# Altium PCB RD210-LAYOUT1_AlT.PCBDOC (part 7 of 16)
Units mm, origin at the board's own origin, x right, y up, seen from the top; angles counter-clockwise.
Board outline 330 x 300 mm, 6 copper layers (TOP, Mid-Layer 1, Mid-Layer 2, Mid-Layer 3, Mid-Layer 4, BOTTOM), stack 1.422 mm thick; 981 components, 463 nets, 2326 pads, 12534 vias.
Unrouted connection lines stored in the file: 6.
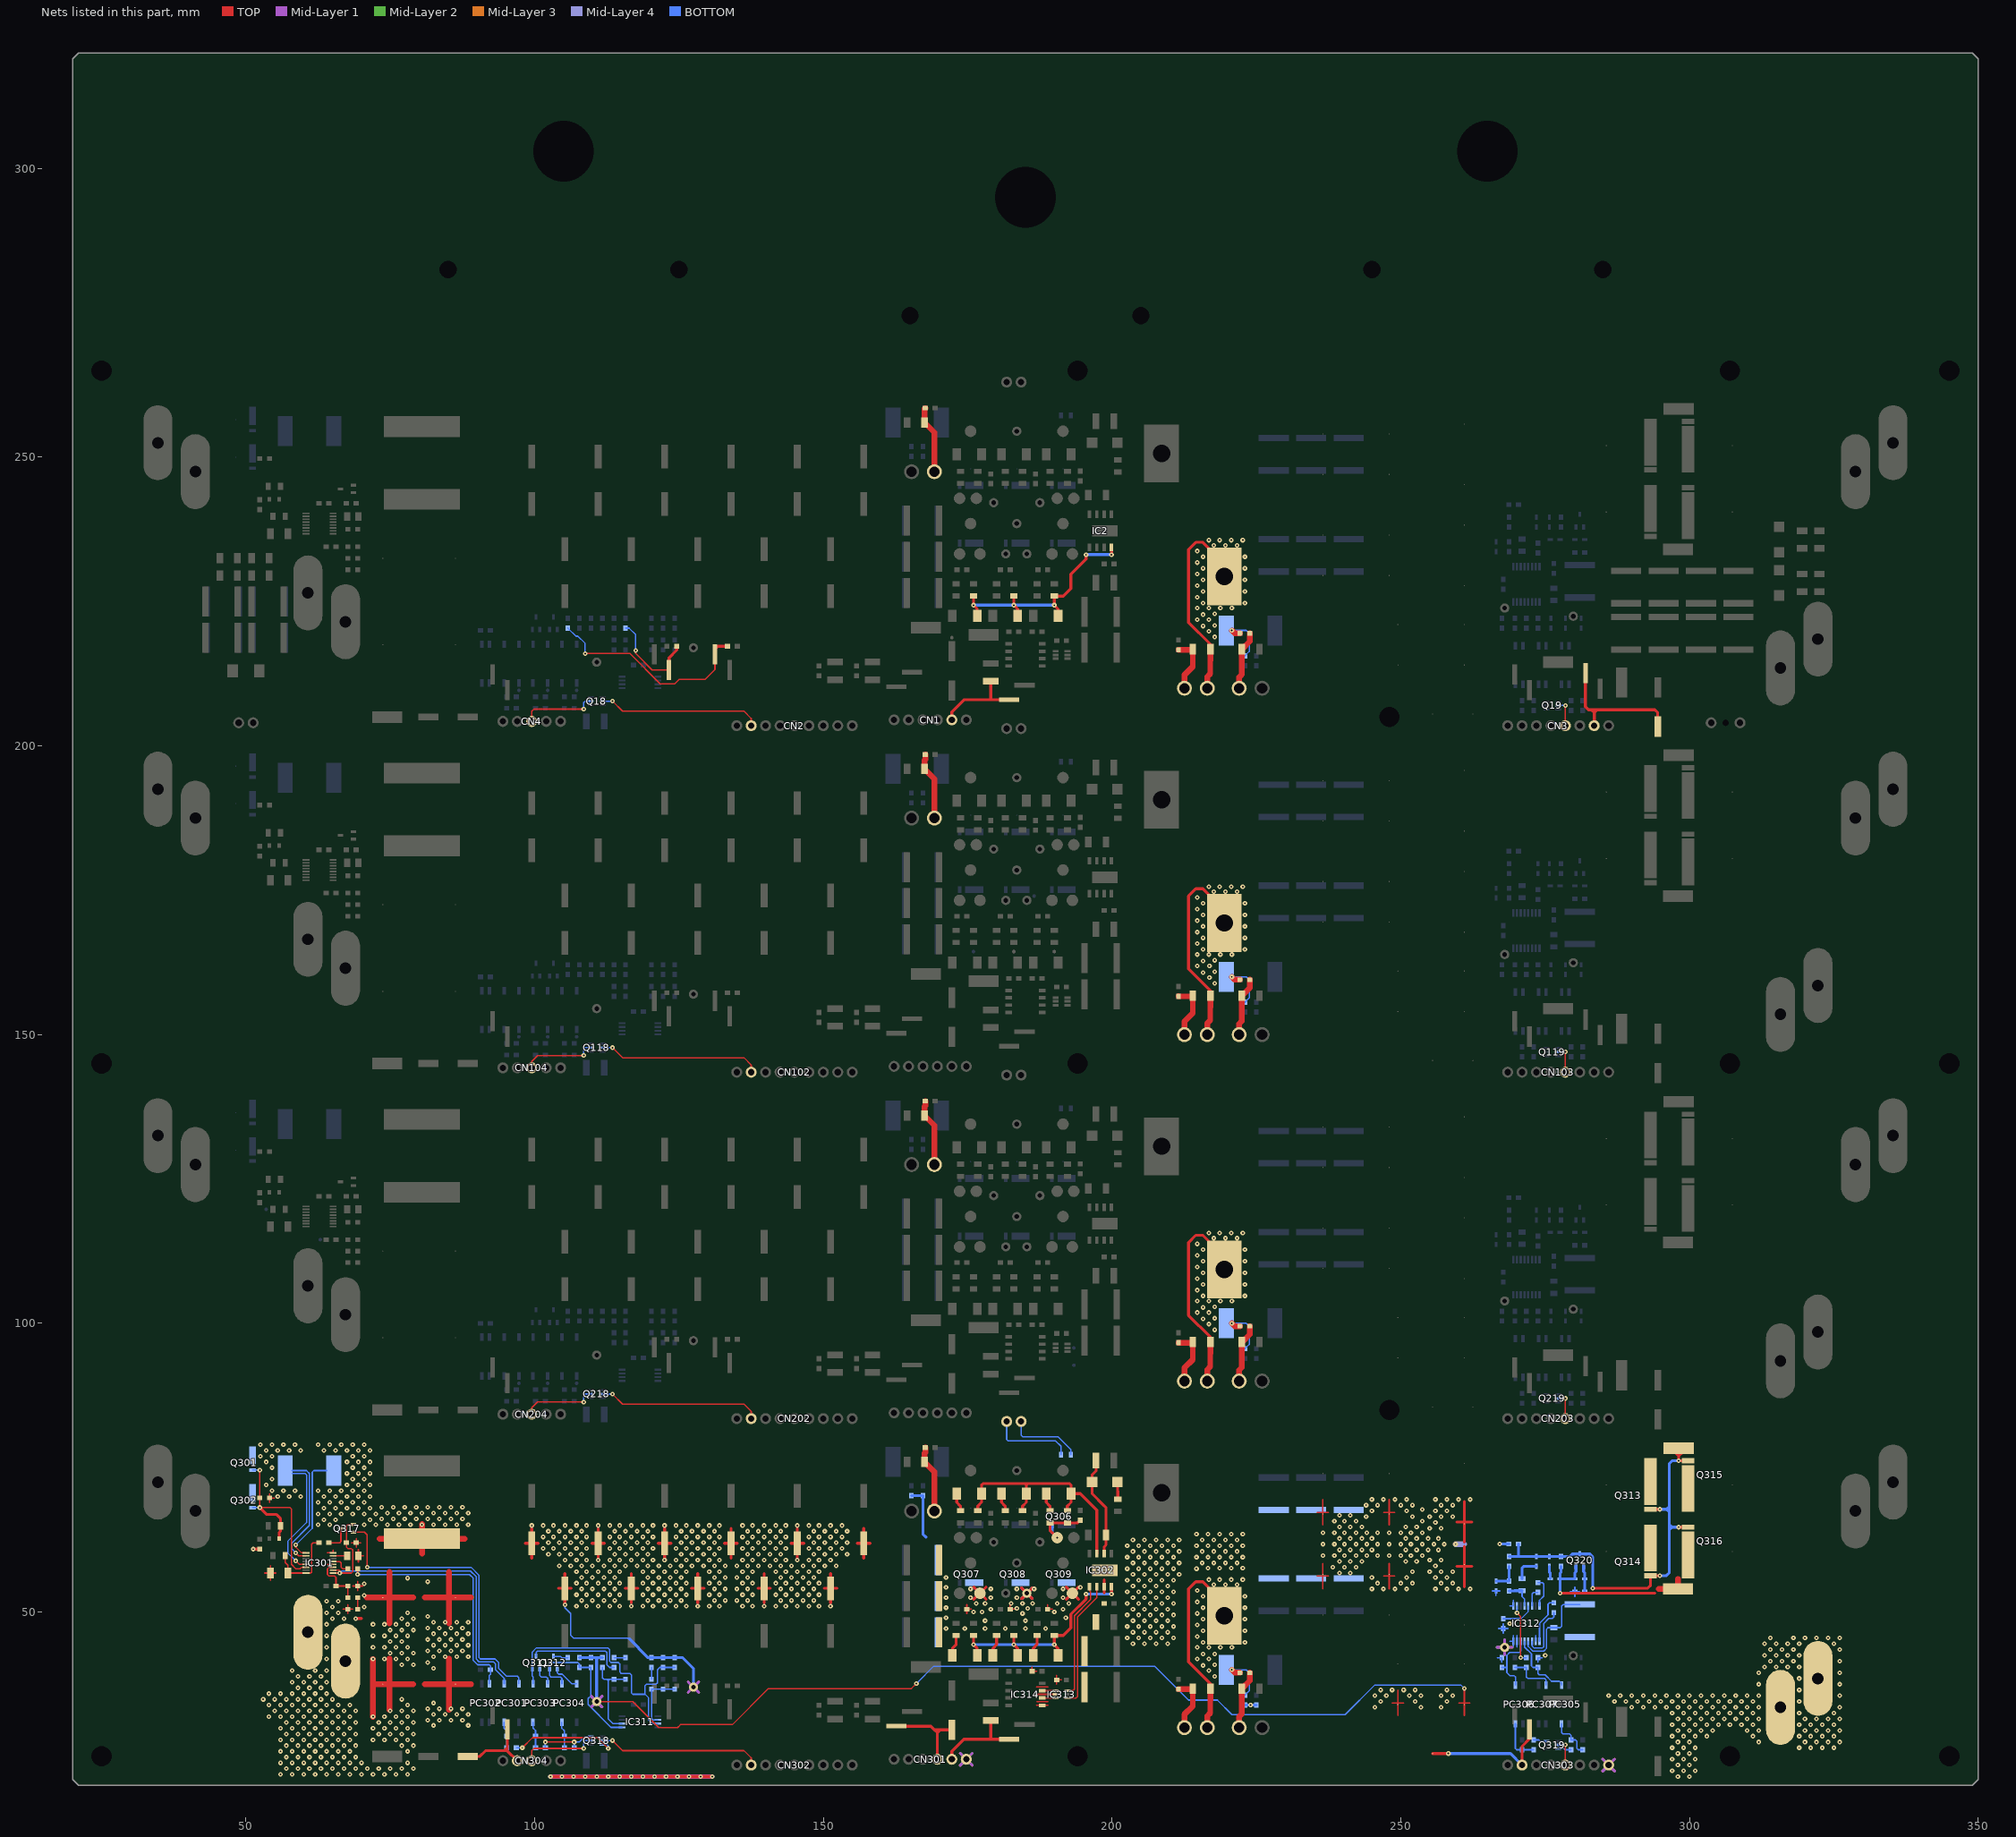
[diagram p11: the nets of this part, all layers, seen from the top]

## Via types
v1: diameter 0.8, hole 0.3, TOP to BOTTOM, 12534 vias

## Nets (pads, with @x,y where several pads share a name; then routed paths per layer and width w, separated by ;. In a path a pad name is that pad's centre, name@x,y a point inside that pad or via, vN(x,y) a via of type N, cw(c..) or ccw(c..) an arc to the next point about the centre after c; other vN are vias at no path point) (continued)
GND_P-4: C311.1 C313.1 C314.2 C315.1 C316.2 C317.2 C318.2 C319.2 C320.2 C321.2 C322.2 C323.2 C324.2 C325.2 C326.2 C327.2 C328.2 C329.1 C330.1 C331.1 C332.1 C333.1 C334.1 C335.1 C336.1 C337.2 C338.2 C339.1 C340.1 C342.2 C343.2 C349.2 C350.2 C351.2 C352.2 C353.2 C354.2 C355.2 C356.2 C357.2 C358.2 C359.1 C360.1 C361.1 C362.1 C363.1 C364.1 C379.1 C381.1 C383.2 C443.2 C447.2 CN301.6 CN303.1 CN316.1 CN317.1 CN320.1 CN334.1 D317.1 IC301.12 IC301.16 IC302.7 IC302.9 IC312.2 IC312.7 IC312.8 IC312.9 IC313.2 IC314.5 Q307.S Q308.S Q309.S R304.1 R322.2 R325.2 R328.2 R350.2 R351.1 R357.2 R358.1 R365.1 R388.1 R389.1 R393.1 TN42.1 TN42.2 TN44.1 TN44.2 TP317.1 TP319.1 | length 650.6
  TOP w0.25: 53.275,56.75 C313.1@54.225,56.75 ; 54.225,55.475 C313.1@54.225,56.75 ; 54.225,58.025 C313.1@54.225,56.75 ; 55.175,56.75 C313.1@54.225,56.75 ; 64.125,58.25 IC301.12@65.1,58.25 ; 64.125,60.25 IC301.16@65.1,60.25 65.1,60.76 ; 66.825,50.5 R304.1@67.65,50.5 ; 67.65,49.725 R304.1@67.65,50.5 ; 67.65,51.275 R304.1@67.65,50.5 ; 68.275,62 R365.1@69.1,62 ; 68.475,50.5 R304.1@67.65,50.5 ; 68.525,54.5 C315.1@69.35,54.5 ; 69.1,61.225 R365.1@69.1,62 ; 69.1,62.775 R365.1@69.1,62 ; 69.35,53.725 C315.1@69.35,54.5 ; 69.35,55.275 C315.1@69.35,54.5 ; 69.475,58.65 C314.2@69.475,59.75 ; 69.475,60.85 C314.2@69.475,59.75 ; 69.925,62 R365.1@69.1,62 ; 70.175,54.5 C315.1@69.35,54.5 ; 70.375,59.75 C314.2@69.475,59.75 ; CN317.1@110.75,34.5 117,34.5 121.5,30 124.75,30 125.25,30.5 134.25,30.5 140.5,36.75 165.25,36.75 v1(166.125,37.625) ; 174.85,49.725 R322.2@174.85,50.5 ; 174.85,51.275 R322.2@174.85,50.5 ; 175.675,50.5 R322.2@174.85,50.5 ; v1@182.35,51.275 R325.2@182.35,50.5 v1@183.175,50.5 ; 186.15,40.525 C340.1@186.15,39.75 186.975,39.75 ; 186.875,37.02 188.875,37.02 ; 186.925,33.845 IC314.5@187.9,33.845 188.875,33.845 ; 187,34.48 188.875,34.48 ; 187,35.75 IC313.2@190.225,35.75 190.89,35.75 191.17,35.47 ; 188.85,51.275 R328.2@188.85,50.5 189.675,50.5 ; 190.4,37.475 C339.1@190.4,38.25 ; 190.4,39.025 C339.1@190.4,38.25 ; 191.225,38.25 C339.1@190.4,38.25 ; 235.523,56.225 236.5,56.225 ; 235.523,67.275 236.5,67.275 ; 236.5,54.023 236.5,56.225 ; 236.5,58.427 C353.2@236.5,56.5 236.5,56.225 ; 236.5,65.073 C351.2@236.5,67 236.5,67.275 ; 236.5,69.477 236.5,67.275 ; 237.477,56.225 236.5,56.225 ; 237.477,67.275 236.5,67.275 ; 247.023,56.225 248,56.225 ; 247.023,67.275 248,67.275 ; 248,54.023 248,56.225 ; 248,58.427 C354.2@248,56.5 248,56.225 ; 248,65.073 C352.2@248,67 248,67.275 ; 248,69.477 248,67.275 ; 248.523,34.275 249.5,34.275 ; 248.977,56.225 248,56.225 ; 248.977,67.275 248,67.275 ; 249.5,32.073 C355.2@249.5,34 249.5,34.275 ; 249.5,36.477 249.5,34.275 ; 250.477,34.275 249.5,34.275 ; 260.023,34.275 261,34.275 ; 261,32.073 C356.2@261,34 261,34.275 ; v1(261,36.75) 261,34.275 ; 261.977,34.275 261,34.275
  TOP w0.5: v1(51.242,60.902) C447.2@52.385,60.902 ; v1(69,48.875) 70,48.875 ; 98.4,61.9 C318.2@99.5,61.9 ; 99.5,59.35 C318.2@99.5,61.9 ; 99.5,64.45 C318.2@99.5,61.9 ; 100.6,61.9 C318.2@99.5,61.9 ; 104.15,54.1 C328.2@105.25,54.1 ; v1(105.25,51.25) C328.2@105.25,54.1 ; 105.25,56.65 C328.2@105.25,54.1 ; 106.35,54.1 C328.2@105.25,54.1 ; 109.9,61.9 C319.2@111,61.9 ; v1@111,59.35 C319.2@111,61.9 ; 111,64.45 C319.2@111,61.9 ; 112.1,61.9 C319.2@111,61.9 ; 115.65,54.1 C327.2@116.75,54.1 ; 116.75,51.55 C327.2@116.75,54.1 ; 116.75,56.65 C327.2@116.75,54.1 ; 117.85,54.1 C327.2@116.75,54.1 ; 121.4,61.9 C320.2@122.5,61.9 ; v1@122.5,59.35 C320.2@122.5,61.9 ; 122.5,64.45 C320.2@122.5,61.9 ; 123.6,61.9 C320.2@122.5,61.9 ; 127.15,54.1 C326.2@128.25,54.1 ; 128.25,51.55 C326.2@128.25,54.1 ; 128.25,56.65 C326.2@128.25,54.1 ; 129.35,54.1 C326.2@128.25,54.1 ; 132.9,61.9 C321.2@134,61.9 ; 134,59.35 C321.2@134,61.9 ; 134,64.45 C321.2@134,61.9 ; 135.1,61.9 C321.2@134,61.9 ; 138.65,54.1 C325.2@139.75,54.1 ; 139.75,51.55 C325.2@139.75,54.1 ; 139.75,56.65 C325.2@139.75,54.1 ; 140.85,54.1 C325.2@139.75,54.1 ; 144.4,61.9 C322.2@145.5,61.9 ; v1@145.5,59.35 C322.2@145.5,61.9 ; 145.5,64.45 C322.2@145.5,61.9 ; 146.6,61.9 C322.2@145.5,61.9 ; 150.15,54.1 C324.2@151.25,54.1 ; 151.25,51.55 C324.2@151.25,54.1 ; 151.25,56.65 C324.2@151.25,54.1 ; 152.35,54.1 C324.2@151.25,54.1 ; 155.9,61.9 C323.2@157,61.9 ; 157,59.35 C323.2@157,61.9 ; 157,64.45 C323.2@157,61.9 ; 158.1,61.9 C323.2@157,61.9 ; 176.064,52.189 TP317.1@177.125,53.25 ; 176.064,54.311 TP317.1@177.125,53.25 ; 178.186,52.189 TP317.1@177.125,53.25 ; 178.186,54.311 TP317.1@177.125,53.25 ; 184.331,52.331 CN334.1@185.25,53.25 ; 184.331,54.169 CN334.1@185.25,53.25 ; 186.125,52.375 CN334.1@185.25,53.25 ; v1@186.169,54.169 CN334.1@185.25,53.25 ; 192.064,52.189 TP319.1@193.125,53.25 ; 192.064,54.311 TP319.1@193.125,53.25 ; 194.186,52.189 TP319.1@193.125,53.25 ; v1@194.186,54.311 TP319.1@193.125,53.25 ; 198.635,53.25 IC302.7@198.635,54.4 198.635,55.55 ; 259.696,57.9 261,57.9 ; 259.696,65.6 261,65.6 ; 261,54.396 261,57.9 ; 261,61.404 C358.2@261,58.25 261,57.9 ; 261,62.096 C357.2@261,65.25 261,65.6 ; 261,69.104 261,65.6 ; 262.304,57.9 261,57.9 ; 262.304,65.6 261,65.6
  TOP w0.6: v1(102.75,21.5) v1(104.75,21.5) v1(106.75,21.5) v1(108.75,21.5) v1(110.75,21.5) v1(112.75,21.5) v1(114.75,21.5) v1(116.75,21.5) v1(118.75,21.5) v1(120.75,21.5) v1(122.75,21.5) v1(124.75,21.5) v1(126.75,21.5) v1(128.75,21.5) v1(130.75,21.5)
  TOP w1: 70.875,52.5 C316.2@73.7,52.5 74.85,52.5 ; v1(72,31.875) 72,37.5 ; v1(72,41.875) 72,37.5 ; v1@74.85,33.043 74.85,37.5 ; 74.85,41.957 74.85,37.5 ; 74.85,48.043 74.85,52.5 ; 74.85,56.957 74.85,52.5 ; 79,37.5 74.85,37.5 ; 79,52.5 74.85,52.5 ; 72,37.5 C317.2@73.7,37.5 74.85,37.5
  Mid-Layer 1 w0.5: 109.831,33.581 CN317.1@110.75,34.5 ; 109.831,35.419 CN317.1@110.75,34.5 ; 111.669,33.581 CN317.1@110.75,34.5 ; 111.669,35.419 CN317.1@110.75,34.5 ; 126.581,36.081 CN316.1@127.5,37 ; 126.581,37.919 CN316.1@127.5,37 ; 128.419,36.081 CN316.1@127.5,37 ; 128.419,37.919 CN316.1@127.5,37 ; 173.725,23.475 CN301.6@174.75,24.5 ; 173.725,25.525 CN301.6@174.75,24.5 ; 175.775,23.475 CN301.6@174.75,24.5 ; 175.775,25.525 CN301.6@174.75,24.5 ; 184.331,52.331 CN334.1@185.25,53.25 ; 184.331,54.169 CN334.1@185.25,53.25 ; 186.169,52.331 CN334.1@185.25,53.25 ; v1@186.169,54.169 CN334.1@185.25,53.25 ; 266.7,43.875 CN320.1@268,43.875 ; 268,42.575 CN320.1@268,43.875 ; 268,45.175 CN320.1@268,43.875 ; 269.3,43.875 CN320.1@268,43.875 ; 284.975,22.475 CN303.1@286,23.5 ; 284.975,24.525 CN303.1@286,23.5 ; 287.025,22.475 CN303.1@286,23.5 ; 287.025,24.525 CN303.1@286,23.5
  Mid-Layer 1 w0.8: v1(102.75,21.5) v1(104.75,21.5) v1(106.75,21.5) v1(108.75,21.5) v1(110.75,21.5) v1(112.75,21.5) v1(114.75,21.5) v1(116.75,21.5) v1(118.75,21.5) v1(120.75,21.5) v1(122.75,21.5) v1(124.75,21.5) v1(126.75,21.5) v1(128.75,21.5) v1(130.75,21.5)
  Mid-Layer 2 w0.5: 173.725,23.475 CN301.6@174.75,24.5 ; 173.725,25.525 CN301.6@174.75,24.5 ; 175.775,23.475 CN301.6@174.75,24.5 ; 175.775,25.525 CN301.6@174.75,24.5 ; 184.331,52.331 CN334.1@185.25,53.25 ; 184.331,54.169 CN334.1@185.25,53.25 ; 186.169,52.331 CN334.1@185.25,53.25 ; v1@186.169,54.169 CN334.1@185.25,53.25 ; 266.7,43.875 CN320.1@268,43.875 ; 268,42.575 CN320.1@268,43.875 ; 268,45.175 CN320.1@268,43.875 ; 269.3,43.875 CN320.1@268,43.875 ; 284.975,22.475 CN303.1@286,23.5 ; 284.975,24.525 CN303.1@286,23.5 ; 287.025,22.475 CN303.1@286,23.5 ; 287.025,24.525 CN303.1@286,23.5
  Mid-Layer 3 w0.5: 173.725,23.475 CN301.6@174.75,24.5 ; 173.725,25.525 CN301.6@174.75,24.5 ; 175.775,23.475 CN301.6@174.75,24.5 ; 175.775,25.525 CN301.6@174.75,24.5 ; 184.331,52.331 CN334.1@185.25,53.25 ; 184.331,54.169 CN334.1@185.25,53.25 ; 186.169,52.331 CN334.1@185.25,53.25 ; v1@186.169,54.169 CN334.1@185.25,53.25 ; 266.7,43.875 CN320.1@268,43.875 ; 268,42.575 CN320.1@268,43.875 ; 268,45.175 CN320.1@268,43.875 ; 269.3,43.875 CN320.1@268,43.875 ; 284.975,22.475 CN303.1@286,23.5 ; 284.975,24.525 CN303.1@286,23.5 ; 287.025,22.475 CN303.1@286,23.5 ; 287.025,24.525 CN303.1@286,23.5
  Mid-Layer 4 w1: v1(259.5,61.75) 261,61.75
  BOTTOM w0.25: v1(105.25,51.25) 105.25,50.75 106.25,49.75 106.25,46 106.75,45.5 116.25,45.5 116.375,45.375 ; v1(166.125,37.625) 169.125,40.625 207.375,40.625 213.25,34.75 218.25,34.75 220.75,32.25 240.375,32.25 245.5,37.375 260.375,37.375 v1(261,36.75) ; 265.875,53.65 D317.1@266.5,53.65 ; 266.5,52.825 D317.1@266.5,53.65 ; 266.725,42.1 R388.1@267.5,42.1 267.5,41.275 ; 266.975,47.15 C383.2@267.75,47.15 ; 267.125,53.65 D317.1@266.5,53.65 ; 267.75,46.325 C383.2@267.75,47.15 ; 267.75,47.975 C383.2@267.75,47.15 ; 268.525,47.15 C383.2@267.75,47.15 ; 268.9,44.95 IC312.8@269.475,44.95 ; 268.9,51.05 IC312.9@269.475,51.05 269.475,52.075 ; 269.475,43.925 IC312.8@269.475,44.95 ; 269.475,45.975 IC312.8@269.475,44.95 ; 270.125,43.925 IC312.7@270.125,44.95 270.125,45.975 ; IC312.2@273.375,44.95 273.375,45.975 ; 273.75,41.275 R389.1@273.75,42.1 274.525,42.1 ; 279.325,53.5 R393.1@280.15,53.5 ; 280.15,52.725 R393.1@280.15,53.5 ; 280.15,54.275 R393.1@280.15,53.5 ; 280.975,53.5 R393.1@280.15,53.5
  BOTTOM w0.5: C379.1@107.75,42.1 R357.2@109.75,42.1 110.5,42.1 ; CN317.1@110.75,34.5 110.75,41.85 ; R358.1@111.75,42.1 111,42.1 ; 116.375,45.375 119.65,42.1 R351.1@120.25,42.1 C311.1@122.25,42.1 R350.2@124.25,42.1 125.65,42.1 127.5,40.25 CN316.1@127.5,37 ; C343.2@165.25,70.15 C342.2@167.25,70.15 167.25,63.5 167.75,63 ; 184.331,52.331 CN334.1@185.25,53.25 ; 184.331,54.169 CN334.1@185.25,53.25 ; 186.169,52.331 CN334.1@185.25,53.25 ; v1@186.169,54.169 CN334.1@185.25,53.25 ; C349.2@223,33.9 v1(224,33.9) C350.2@225,33.9 ; 266.7,43.875 CN320.1@268,43.875 268,45.175 ; v1(267.142,61.775) C443.2@268.705,61.775 ; 110.5,42.1 110.75,41.85 ; 110.5,42.1 111,42.1 ; 110.75,41.85 111,42.1
  BOTTOM w0.6: v1(102.75,21.5) v1(104.75,21.5) v1(106.75,21.5) v1(108.75,21.5) v1(110.75,21.5) v1(112.75,21.5) v1(114.75,21.5) v1(116.75,21.5) v1(118.75,21.5) v1(120.75,21.5) v1(122.75,21.5) v1(124.75,21.5) v1(126.75,21.5) v1(128.75,21.5) v1(130.75,21.5)
  other v1: 298,21.5 300,21.5 56,21.875 58,21.875 60,21.875 62,21.875 64,21.875 66,21.875 68,21.875 70,21.875 72,21.875 74,21.875 76,21.875 78,21.875 297,22.5 299,22.5 301,22.5 57,22.875 59,22.875 61,22.875 63,22.875 65,22.875 67,22.875 69,22.875 71,22.875 73,22.875 75,22.875 77,22.875 79,22.875 298,23.5 300,23.5 56,23.875 58,23.875 60,23.875 62,23.875 64,23.875 66,23.875 68,23.875 70,23.875 78,23.875 297,24.5 299,24.5 301,24.5 57,24.875 59,24.875 61,24.875 63,24.875 65,24.875 67,24.875 69,24.875 298,25.5 300,25.5 56,25.875 58,25.875 60,25.875 62,25.875 64,25.875 66,25.875 68,25.875 78,25.875 297,26.5 299,26.5 301,26.5 319,26.5 321,26.5 323,26.5 325,26.5 57,26.875 59,26.875 61,26.875 63,26.875 65,26.875 67,26.875 69,26.875 77,26.875 79,26.875 298,27.5 300,27.5 312,27.5 320,27.5 322,27.5 324,27.5 326,27.5 56,27.875 58,27.875 60,27.875 62,27.875 64,27.875 66,27.875 68,27.875 72,27.875 74,27.875 76,27.875 78,27.875 297,28.5 299,28.5 301,28.5 303,28.5 311,28.5 319,28.5 321,28.5 323,28.5 325,28.5 57,28.875 59,28.875 61,28.875 63,28.875 65,28.875 67,28.875 69,28.875 73,28.875 75,28.875 77,28.875 79,28.875 298,29.5 300,29.5 302,29.5 304,29.5 310,29.5 312,29.5 320,29.5 322,29.5 324,29.5 326,29.5 56,29.875 58,29.875 60,29.875 62,29.875 64,29.875 66,29.875 68,29.875 72,29.875 74,29.875 76,29.875 78,29.875 297,30.5 299,30.5 301,30.5 303,30.5 305,30.5 307,30.5 309,30.5 311,30.5 319,30.5 321,30.5 323,30.5 325,30.5 57,30.875 59,30.875 61,30.875 63,30.875 65,30.875 67,30.875 69,30.875 73,30.875 75,30.875 77,30.875 79,30.875 298,31.5 300,31.5 302,31.5 304,31.5 306,31.5 308,31.5 310,31.5 312,31.5 320,31.5 322,31.5 324,31.5 326,31.5 54,31.875 56,31.875 58,31.875 60,31.875 62,31.875 64,31.875 66,31.875 68,31.875 74,31.875 76,31.875 78,31.875 297,32.5 299,32.5 301,32.5 303,32.5 305,32.5 307,32.5 309,32.5 311,32.5 319,32.5 325,32.5 55,32.875 57,32.875 59,32.875 61,32.875 63,32.875 65,32.875 67,32.875 69,32.875 75,32.875 77,32.875 79,32.875 245.5,33.5 253.5,33.5 257,33.5 290,33.5 292,33.5 294,33.5 296,33.5 298,33.5 300,33.5 302,33.5 304,33.5 306,33.5 308,33.5 310,33.5 312,33.5 326,33.5 54,33.875 56,33.875 58,33.875 60,33.875 62,33.875 64,33.875 66,33.875 68,33.875 78,33.875 246.5,34.5 252.5,34.5 258,34.5 287,34.5 289,34.5 291,34.5 293,34.5 295,34.5 297,34.5 299,34.5 301,34.5 303,34.5 305,34.5 307,34.5 309,34.5 311,34.5 319,34.5 53,34.875 55,34.875 57,34.875 59,34.875 61,34.875 63,34.875 65,34.875 77,34.875 245.5,35.5 247.5,35.5 251.5,35.5 253.5,35.5 257,35.5 259,35.5 286,35.5 288,35.5 290,35.5 292,35.5 294,35.5 296,35.5 298,35.5 300,35.5 302,35.5 304,35.5 306,35.5 308,35.5 310,35.5 312,35.5 326,35.5 54,35.875 56,35.875 58,35.875 60,35.875 62,35.875 64,35.875 246.5,36.5 248.5,36.5 250.5,36.5 252.5,36.5 258,36.5 319,36.5 59,36.875 61,36.875 63,36.875 312,37.5 326,37.5 58,37.875 60,37.875 62,37.875 64,37.875 319,38.5 59,38.875 61,38.875 63,38.875 312,39.5 326,39.5 58,39.875 62,39.875 64,39.875 313,40.5 315,40.5 317,40.5 319,40.5 77,40.875 79,40.875 314,41.5 316,41.5 318,41.5 326,41.5 64,41.875 74,41.875 76,41.875 78,41.875 275,42.5 313,42.5 315,42.5 317,42.5 319,42.5 75,42.875 77,42.875 79,42.875 314,43.5 316,43.5 318,43.5 326,43.5 64,43.875 72,43.875 74,43.875 76,43.875 78,43.875 203.625,44.5 205.625,44.5 207.625,44.5 209.625,44.5 313,44.5 315,44.5 317,44.5 319,44.5 325,44.5 75,44.875 77,44.875 202.625,45.5 204.625,45.5 206.625,45.5 208.625,45.5 210.625,45.5 314,45.5 318,45.5 320,45.5 322,45.5 324,45.5 326,45.5 64,45.875 72,45.875 74,45.875 76,45.875 78,45.875 203.625,46.5 205.625,46.5 207.625,46.5 209.625,46.5 75,46.875 77,46.875 79,46.875 171.25,47.125 174.5,47.125 178,47.125 181.5,47.125 185,47.125 188.5,47.125 202.625,47.5 204.625,47.5 206.625,47.5 208.625,47.5 210.625,47.5 64,47.875 72,47.875 74,47.875 76,47.875 78,47.875 268.875,48 178,48.5 185,48.5 203.625,48.5 205.625,48.5 207.625,48.5 209.625,48.5 65,48.875 67,48.875 77,48.875 79,48.875 171.25,49 192,49 202.625,49.5 204.625,49.5 206.625,49.5 208.625,49.5 210.625,49.5 184.5,49.75 64,49.875 66,49.875 78,49.875 176,50 177.5,50 190,50 179,50.5 191.5,50.5 203.625,50.5 205.625,50.5 207.625,50.5 209.625,50.5 183.5,50.625 185.375,50.625 171.25,50.75 65,50.875 70.5,50.875 107.25,51 109,51 111,51 113,51 114.75,51 116.75,51 118.75,51 120.5,51 122.5,51 124.5,51 126.25,51 128.25,51 130.25,51 132,51 136,51 137.75,51 139.75,51 141.75,51 143.5,51 145.5,51 147.5,51 149.25,51 151.25,51 176.5,51.5 178,51.5 182.5,51.5 184.5,51.5 186.25,51.5 190.5,51.5 192.5,51.5 202.625,51.5 204.625,51.5 206.625,51.5 208.625,51.5 210.625,51.5 64,51.875 66,51.875 108.125,52 110,52 112,52 113.875,52 119.625,52 121.5,52 123.5,52 125.375,52 131.125,52 133,52 135,52 136.875,52 142.625,52 144.5,52 146.5,52 148.375,52 171.25,52.5 175.5,52.5 179,52.5 183.5,52.5 191.5,52.5 203.625,52.5 205.625,52.5 207.625,52.5 209.625,52.5 70.5,52.875 107.25,53 109,53 111,53 113,53 114.75,53 118.75,53 120.5,53 122.5,53 124.5,53 126.25,53 130.25,53 132,53 136,53 137.75,53 141.75,53 143.5,53 145.5,53 147.5,53 149.25,53 202.625,53.5 204.625,53.5 206.625,53.5 208.625,53.5 210.625,53.5 108.125,54 110,54 112,54 113.875,54 119.625,54 121.5,54 123.5,54 125.375,54 131.125,54 133,54 135,54 136.875,54 142.625,54 144.5,54 146.5,54 148.375,54 175.5,54 179,54 183.5,54 186.5,54 191.5,54 245,54 247,54 249,54 251,54 256,54 258,54 260,54 262,54 171.25,54.25 194.5,54.25 203.625,54.5 205.625,54.5 207.625,54.5 209.625,54.5 70.5,54.875 107.25,55 109,55 111,55 113,55 114.75,55 118.75,55 120.5,55 122.5,55 124.5,55 126.25,55 130.25,55 132,55 136,55 137.75,55 141.75,55 143.5,55 145.5,55 147.5,55 149.25,55 246,55 250,55 252,55 257,55 259,55 202.625,55.5 204.625,55.5 206.625,55.5 208.625,55.5 210.625,55.5 78,55.875 108.125,56 110,56 112,56 113.875,56 119.625,56 121.5,56 123.5,56 125.375,56 131.125,56 133,56 135,56 136.875,56 142.625,56 144.5,56 146.5,56 148.375,56 171.25,56 245,56 251,56 256,56 258,56 203.625,56.5 205.625,56.5 207.625,56.5 209.625,56.5 211.625,56.5 239.375,56.75 241.25,56.75 107.25,57 109,57 111,57 113,57 114.75,57 118.75,57 120.5,57 122.5,57 124.5,57 126.25,57 130.25,57 132,57 136,57 137.75,57 141.75,57 143.5,57 145.5,57 147.5,57 149.25,57 252,57 255,57 257,57 259,57 202.625,57.5 204.625,57.5 206.625,57.5 208.625,57.5 210.625,57.5 214.625,57.5 216.625,57.625 218.625,57.625 220.625,57.625 222.625,57.625 238.25,57.75 240.25,57.75 242.25,57.75 104.25,58 106.25,58 108.125,58 110,58 112,58 113.875,58 115.75,58 117.75,58 119.625,58 121.5,58 123.5,58 125.375,58 127.25,58 129.25,58 131.125,58 133,58 135,58 136.875,58 138.75,58 140.75,58 142.625,58 144.5,58 146.5,58 148.375,58 150.25,58 152.25,58 256,58 203.625,58.5 205.625,58.5 207.625,58.5 209.625,58.5 211.625,58.5 215.625,58.5 217.625,58.5 219.625,58.5 221.625,58.5 239.375,58.75 241.25,58.75 243.25,58.75 250.875,58.75 252.75,58.75 105.25,59 107.25,59 109,59 111,59 113,59 114.75,59 116.75,59 118.75,59 120.5,59 122.5,59 124.5,59 126.25,59 128.25,59 130.25,59 132,59 136,59 137.75,59 139.75,59 141.75,59 143.5,59 145.5,59 147.5,59 149.25,59 151.25,59 255,59 257,59 202.625,59.5 204.625,59.5 206.625,59.5 208.625,59.5 210.625,59.5 214.625,59.5 216.625,59.5 218.625,59.5 220.625,59.5 222.625,59.5 236.5,59.75 238.5,59.75 240.25,59.75 242.25,59.75 244.125,59.75 246,59.75 248,59.75 250,59.75 251.75,59.75 253.75,59.75 102.375,60 104.25,60 106.25,60 108.125,60 113.875,60 115.75,60 117.75,60 119.625,60 125.375,60 127.25,60 129.25,60 131.125,60 136.875,60 138.75,60 140.75,60 142.625,60 148.375,60 150.25,60 152.25,60 154.125,60 203.625,60.5 205.625,60.5 207.625,60.5 209.625,60.5 211.625,60.5 215.625,60.5 217.625,60.5 219.625,60.5 221.625,60.5 239.375,60.75 241.25,60.75 243.25,60.75 245,60.75 250.875,60.75 252.75,60.75 254.75,60.75 256.5,60.75 101.5,61 103.25,61 105.25,61 107.25,61 109,61 113,61 114.75,61 116.75,61 118.75,61 120.5,61 124.5,61 126.25,61 128.25,61 130.25,61 132,61 136,61 137.75,61 139.75,61 141.75,61 143.5,61 147.5,61 149.25,61 151.25,61 153.25,61 202.625,61.5 204.625,61.5 206.625,61.5 208.625,61.5 210.625,61.5 214.625,61.5 216.625,61.5 218.625,61.5 220.625,61.5 222.625,61.5 236.5,61.75 238.5,61.75 240.25,61.75 242.25,61.75 244.125,61.75 246,61.75 248,61.75 250,61.75 251.75,61.75 253.75,61.75 255.75,61.75 257.5,61.75 102.375,62 104.25,62 106.25,62 108.125,62 113.875,62 115.75,62 117.75,62 119.625,62 125.375,62 127.25,62 129.25,62 131.125,62 136.875,62 138.75,62 140.75,62 142.625,62 148.375,62 150.25,62 152.25,62 154.125,62 203.625,62.5 205.625,62.5 207.625,62.5 209.625,62.5 211.625,62.5 215.625,62.5 217.625,62.5 219.625,62.5 221.625,62.5 239.375,62.75 241.25,62.75 243.25,62.75 245,62.75 250.875,62.75 252.75,62.75 254.75,62.75 256.5,62.75 101.5,63 103.25,63 105.25,63 107.25,63 109,63 113,63 114.75,63 116.75,63 118.75,63 120.5,63 124.5,63 126.25,63 128.25,63 130.25,63 132,63 136,63 137.75,63 139.75,63 141.75,63 143.5,63 147.5,63 149.25,63 151.25,63 153.25,63 214.625,63.5 216.625,63.5 218.625,63.5 220.625,63.5 222.625,63.5 236.5,63.75 238.5,63.75 240.25,63.75 242.25,63.75 244.125,63.75 246,63.75 248,63.75 250,63.75 251.75,63.75 253.75,63.75 102.375,64 104.25,64 106.25,64 108.125,64 113.875,64 115.75,64 117.75,64 119.625,64 125.375,64 127.25,64 129.25,64 131.125,64 136.875,64 138.75,64 140.75,64 142.625,64 148.375,64 150.25,64 152.25,64 154.125,64 255,64.5 257,64.5 239.375,64.75 241.25,64.75 243.25,64.75 250.875,64.75 252.75,64.75 99.5,65 101.5,65 103.25,65 105.25,65 107.25,65 109,65 111,65 113,65 114.75,65 116.75,65 118.75,65 120.5,65 122.5,65 124.5,65 126.25,65 128.25,65 130.25,65 132,65 136,65 137.75,65 139.75,65 141.75,65 143.5,65 145.5,65 147.5,65 149.25,65 151.25,65 153.25,65 256,65.5 238.5,65.75 240.25,65.75 242.25,65.75 253.75,65.75 244,66.5 252,66.5 255,66.5 257,66.5 259,66.5 239.375,66.75 241.25,66.75 245,67.5 251,67.5 256,67.5 258,67.5 253.75,67.75 244,68.5 246,68.5 250,68.5 252,68.5 257,68.5 259,68.5 245,69.5 247,69.5 249,69.5 251,69.5 256,69.5 258,69.5 260,69.5 262,69.5
H_EN_0-1: CN4.3 Q18.2 | length 13.4
  TOP w0.25: CN4.3@99.5,204.25 99.5,206 99.875,206.375 v1(108.5,206.375)
  BOTTOM w0.25: v1(108.5,206.375) 108.5,207.5 108.75,207.75 Q18.2@109.725,207.75
H_EN_0-2: CN104.3 Q118.2 | length 13
  TOP w0.25: CN104.3@99.5,144.25 99.5,145.375 100.5,146.375 v1(108.5,146.375)
  BOTTOM w0.25: v1(108.5,146.375) 108.5,147.5 108.75,147.75 Q118.2@109.725,147.75
H_EN_0-3: CN204.3 Q218.2 | length 13
  TOP w0.25: CN204.3@99.5,84.25 99.5,85.375 100.5,86.375 v1(108.5,86.375)
  BOTTOM w0.25: v1(108.5,86.375) 108.5,87.5 108.75,87.75 Q218.2@109.725,87.75
H_EN_0-4: CN304.3 Q318.2 | length 13.4
  TOP w0.25: CN304.3@99.5,24.25 99.5,26 99.875,26.375 v1(108.5,26.375)
  BOTTOM w0.25: v1(108.5,26.375) 108.5,27.5 108.75,27.75 Q318.2@109.725,27.75
I_SEN_N_3-1: C49.1 C405.2 CN10.1 L2.2 R38.1 R402.1 | length 45.3
  TOP w0.5: C405.2@217.025,216.75 217.025,217.6 213.25,221.375 213.25,234 214.5,235.25 215.75,235.25 219.434,231.566 L2.2@219.434,229.336
  TOP w1: CN10.1@216.48,210 216.48,211.98 217,212.5 C405.2@217.025,216.75 ; v1(220.75,220) 221.25,219.5 R402.1@222.15,219.5
  BOTTOM w0.25: v1(220.75,220) 223.25,220 223.75,219.5 223.75,216.35 C49.1@223,215.6
  other v1: 217.75,218.875 216.75,219.875 215.75,220.75 217.75,220.875 214.75,221.875 216.75,221.875 215.75,222.75 217.75,222.875 214.75,223.875 216.75,223.875 218.75,223.875 220.75,223.875 215.75,224.75 223,224.75 214.75,225.75 215.75,226.75 223,226.75 214.75,227.75 215.75,228.75 223,228.75 214.75,229.75 215.75,230.75 223,230.75 214.75,231.75 215.75,232.75 223,232.75 214.75,233.75 217.625,234.75 219.625,234.75 221.625,234.75 216.75,235.625 218.625,235.625 220.625,235.625 222.625,235.625
I_SEN_N_3-2: C149.1 C415.2 CN110.1 L102.2 R138.1 R412.1 | length 45.3
  TOP w0.5: C415.2@217.025,156.75 217.025,157.6 213.25,161.375 213.25,174 214.5,175.25 215.75,175.25 219.434,171.566 L102.2@219.434,169.336
  TOP w1: CN110.1@216.48,150 216.48,151.98 217,152.5 C415.2@217.025,156.75 ; v1(220.75,160) 221.25,159.5 R412.1@222.15,159.5
  BOTTOM w0.25: v1(220.75,160) 223.25,160 223.75,159.5 223.75,156.35 C149.1@223,155.6
  other v1: 217.75,158.875 216.875,159.875 215.75,160.75 217.75,160.875 214.75,161.875 216.875,161.875 215.75,162.75 217.75,162.875 214.75,163.875 216.75,163.875 218.75,163.875 220.75,163.875 215.75,164.75 223,164.75 214.75,165.75 215.75,166.75 223,166.75 214.75,167.75 215.75,168.75 223,168.75 214.75,169.75 215.75,170.75 223,170.75 214.75,171.75 215.75,172.75 223,172.75 214.75,173.75 217.625,174.75 219.625,174.75 221.625,174.75 216.75,175.625 218.625,175.625 220.625,175.625 222.625,175.625
I_SEN_N_3-3: C249.1 C425.2 CN210.1 L202.2 R238.1 R422.1 | length 45.3
  TOP w0.5: C425.2@217.025,96.75 217.025,97.6 213.25,101.375 213.25,114 214.5,115.25 215.75,115.25 219.434,111.566 L202.2@219.434,109.336
  TOP w1: CN210.1@216.48,90 216.48,91.98 217,92.5 C425.2@217.025,96.75 ; v1(220.75,100) 221.25,99.5 R422.1@222.15,99.5
  BOTTOM w0.25: v1(220.75,100) 223.25,100 223.75,99.5 223.75,96.35 C249.1@223,95.6
  other v1: 217.75,98.875 216.75,99.875 215.75,100.75 217.75,100.875 214.75,101.875 216.75,101.875 215.75,102.75 217.75,102.875 214.75,103.875 216.75,103.875 218.75,103.875 220.75,103.875 215.75,104.75 223,104.75 214.75,105.75 215.75,106.75 223,106.75 214.75,107.75 215.75,108.75 223,108.75 214.75,109.75 215.75,110.75 223,110.75 214.75,111.75 215.75,112.75 223,112.75 214.75,113.75 217.625,114.75 219.625,114.75 221.625,114.75 216.75,115.625 218.625,115.625 220.625,115.625 222.625,115.625
I_SEN_N_3-4: C349.1 C435.2 CN310.1 L302.2 R338.1 R432.1 | length 45.3
  TOP w0.5: C435.2@217.025,36.75 217.025,37.6 213.25,41.375 213.25,54 214.5,55.25 215.75,55.25 219.434,51.566 L302.2@219.434,49.336
  TOP w1: CN310.1@216.48,30 216.48,31.98 217,32.5 C435.2@217.025,36.75 ; v1(220.75,40) 221.25,39.5 R432.1@222.15,39.5
  BOTTOM w0.25: v1(220.75,40) 223.25,40 223.75,39.5 223.75,36.35 C349.1@223,35.6
  other v1: 217.75,38.875 216.75,39.875 215.75,40.75 217.75,40.875 214.75,41.875 216.75,41.875 215.75,42.75 217.75,42.75 214.75,43.875 216.75,43.875 218.75,43.875 220.75,43.875 215.75,44.75 223,44.75 214.75,45.75 215.75,46.75 223,46.75 214.75,47.75 215.75,48.75 223,48.75 214.75,49.75 215.75,50.75 223,50.75 214.75,51.75 215.75,52.75 223,52.75 214.75,53.75 217.625,54.75 219.625,54.75 221.625,54.75 216.75,55.625 218.625,55.625 220.625,55.625 222.625,55.625
I_SEN_P_1-1: C401.2 CN8.2 R401.2 | length 11.8
  TOP w1: R401.2@167.65,258.5 167.525,258.375 C401.2@167.525,256 169.23,254.295 CN8.2@169.23,247.5
I_SEN_P_1-2: C411.2 CN108.2 R411.2 | length 11.8
  TOP w1: R411.2@167.65,198.5 167.65,197.65 167.5,197.5 167.5,196.025 C411.2@167.525,196 167.525,195.975 169.23,194.27 CN108.2@169.23,187.5
I_SEN_P_1-3: C421.2 CN208.2 R421.2 | length 11.8
  TOP w1: R421.2@167.65,138.5 167.65,137.65 167.5,137.5 167.5,136.025 C421.2@167.525,136 169.25,134.275 169.25,127.52 CN208.2@169.23,127.5
I_SEN_P_1-4: C431.2 CN308.2 R431.2 | length 11.8
  TOP w1: R431.2@167.65,78.5 167.65,77.65 167.5,77.5 167.5,76.025 C431.2@167.525,76 167.525,75.975 169.23,74.27 CN308.2@169.23,67.5
I_SEN_P_2-1: C403.1 CN9.2 R402.2 | length 10.3
  TOP w0.5: CN9.2@222.02,209.98 CN9.2@222.02,210
  TOP w1: CN9.2@222.02,210 222,210.02 222,211.875 222.475,212.35 C403.1@222.475,216.75 222.5,216.75 223.85,218.1 R402.2@223.85,219.5
I_SEN_P_2-2: C413.1 CN109.2 R412.2 | length 10.3
  TOP w0.5: CN109.2@222.02,149.98 CN109.2@222.02,150 CN109.2@222.02,150.02
  TOP w1: CN109.2@222.02,150 222,150.02 222,151.875 222.475,152.35 C413.1@222.475,156.75 222.5,156.75 223.85,158.1 R412.2@223.85,159.5
I_SEN_P_2-3: C423.1 CN209.2 R422.2 | length 10.3
  TOP w0.5: CN209.2@222.02,89.98 CN209.2@222.02,90
  TOP w1: CN209.2@222.02,90 222,90.02 222,91.875 222.475,92.35 C423.1@222.475,96.75 222.5,96.75 223.85,98.1 R422.2@223.85,99.5
I_SEN_P_2-4: C433.1 CN309.2 R432.2 | length 10.3
  TOP w0.5: CN309.2@222.02,29.98 CN309.2@222.02,30
  TOP w1: CN309.2@222.02,30 222,30.02 222,31.875 222.475,32.35 C433.1@222.475,36.75 222.5,36.75 223.85,38.1 R432.2@223.85,39.5
I_SEN_P_3-1: C405.1 CN10.2 R403.2 | length 9.9
  TOP w1: R403.2@211.5,216.65 211.525,216.625 213.85,216.625 C405.1@213.975,216.75 213.975,213.725 212.52,212.27 CN10.2@212.52,210
I_SEN_P_3-2: C415.1 CN110.2 R413.2 | length 9.9
  TOP w1: R413.2@211.5,156.65 211.525,156.625 213.85,156.625 C415.1@213.975,156.75 213.975,153.725 212.52,152.27 CN110.2@212.52,150
I_SEN_P_3-3: C425.1 CN210.2 R423.2 | length 9.9
  TOP w1: R423.2@211.5,96.65 211.525,96.625 213.85,96.625 C425.1@213.975,96.75 213.975,93.725 212.52,92.27 CN210.2@212.52,90
I_SEN_P_3-4: C435.1 CN310.2 R433.2 | length 9.9
  TOP w1: R433.2@211.5,36.65 211.525,36.625 213.85,36.625 C435.1@213.975,36.75 213.975,33.725 212.52,32.27 CN310.2@212.52,30
L_IN1_0-1: CN3.4 Q19.2 | length 4.7
  TOP w0.25: CN3.4@278.5,203.5 v1(278.5,207)
  BOTTOM w0.25: Q19.2@277.275,207 v1(278.5,207)
L_IN1_0-2: CN103.4 Q119.2 | length 4.7
  TOP w0.25: CN103.4@278.5,143.5 v1(278.5,147)
  BOTTOM w0.25: Q119.2@277.275,147 v1(278.5,147)
L_IN1_0-3: CN203.4 Q219.2 | length 4.7
  TOP w0.25: CN203.4@278.5,83.5 v1(278.5,87)
  BOTTOM w0.25: Q219.2@277.275,87 v1(278.5,87)
L_IN1_0-4: CN303.4 Q319.2 | length 4.7
  TOP w0.25: CN303.4@278.5,23.5 v1(278.5,27)
  BOTTOM w0.25: Q319.2@277.275,27 v1(278.5,27)
MES_EN_0-1: CN2.8 Q18.5 | length 28.2
  TOP w0.25: v1(113.5,207.75) 115.25,206 136.25,206 137.5,204.75 CN2.8@137.5,203.5
  BOTTOM w0.25: Q18.5@111.775,207.75 v1(113.5,207.75)
MES_EN_0-2: CN102.8 Q118.5 | length 28.2
  TOP w0.25: v1(113.5,147.75) 115.25,146 136.25,146 137.5,144.75 CN102.8@137.5,143.5
  BOTTOM w0.25: Q118.5@111.775,147.75 v1(113.5,147.75)
MES_EN_0-3: CN202.8 Q218.5 | length 28.2
  TOP w0.25: v1(113.5,87.75) 115.25,86 136.25,86 137.5,84.75 CN202.8@137.5,83.5
  BOTTOM w0.25: Q218.5@111.775,87.75 v1(113.5,87.75)
MES_EN_0-4: CN302.8 Q318.5 | length 28.2
  TOP w0.25: v1(113.5,27.75) 115.25,26 136.25,26 137.5,24.75 CN302.8@137.5,23.5
  BOTTOM w0.25: Q318.5@111.775,27.75 v1(113.5,27.75)
N00100002: Q306.G R316.2 R317.2 R318.1 TP326.1 | length 11.1
  TOP w0.5: v1(190.5,62.875) 189.25,64.125 R316.2@189.25,65.45 R317.2@192.25,65.45 194.05,65.45 R318.1@194.5,65.9
  BOTTOM w0.5: Q306.G@189.595,65.1 189.595,63.78 v1(190.5,62.875)
N00100007: CN19.2 R47.1 R48.1 | length 17.3
  TOP w0.25: v1(117.5,216.5) 117.5,216 120.35,213.15 CN19.2@123.27,213.15 ; R47.1@124.6,217.25 R47.1@124.6,217.5
  TOP w0.5: CN19.2@123.27,213.15 123.27,215.27 124.6,216.6 R47.1@124.6,217.25
  BOTTOM w0.25: R48.1@115.75,220.4 116.35,220.4 117.5,219.25 v1(117.5,216.5)
N00100012: C99.1 CN1.5 CN12.1 | length 15.8
  TOP w0.5: CN1.5@172.25,204.5 172.25,205.875 174.355,207.98 178.75,207.98 ; C99.1@179,211.225 179,208.23 ; CN12.1@182.15,207.98 179.25,207.98 ; 178.75,207.98 179,208.23 ; 178.75,207.98 179.25,207.98 ; 179,208.23 179.25,207.98
N00100017: CN18.2 R55.1 R56.1 | length 37.4
  TOP w0.25: v1(108.75,216) 116.5,216 121.75,210.75 124.25,210.75 125,211.5 129.5,211.5 131.23,213.23 CN18.2@131.23,215.85
  TOP w0.5: CN18.2@131.23,215.85 131.23,216.73 131.75,217.25 R55.1@133.4,217.25
  BOTTOM w0.25: R56.1@105.75,220.4 107.15,219 107.5,219 108.75,217.75 v1(108.75,216)
N00100018: C376.1 IC311.2 R352.2 R353.1 | length 10.3
  BOTTOM w0.25: IC311.2@121.35,31.325 120.5,31.325 120.25,31.575 R352.2@120.25,36.65 C376.1@122.25,36.65 R353.1@124.25,36.65
N00100020: C311.2 IC311.3 PC303.4 Q311.2 R350.1 | length 48.7
  BOTTOM w0.25: PC303.4@99.73,37.6 99.73,38.75 99.6,38.88 Q311.2@99.6,40.15 99.6,43.1 100.25,43.75 112.75,43.75 113,43.5 113,41.5 113.25,41.25 114.5,41.25 114.75,41 114.75,39.625 115,39.375 116.5,39.375 116.75,39.125 116.75,36 117,35.75 118.875,35.75 ; IC311.3@121.35,30.675 120.325,30.675 119.75,31.25 119.75,35.125 119.125,35.75 ; R350.1@124.25,40.4 C311.2@122.25,40.4 121.65,40.4 121.25,40 121.25,37.75 121,37.5 119.375,37.5 119.125,37.25 119.125,36 ; 118.875,35.75 119.125,36 ; 118.875,35.75 119.125,35.75 ; 119.125,35.75 119.125,36
N00100023: C380.1 IC311.6 R358.2 R359.1 | length 16
  BOTTOM w0.25: R358.2@111.75,40.4 111.75,38.6 112,38.35 112.5,38.35 ; IC311.6@115.15,30.675 113.575,30.675 112.75,31.5 112.75,38.1 ; R359.1@115.75,38.35 C380.1@113.75,38.35 113,38.35 ; 112.5,38.35 112.75,38.1 ; 112.5,38.35 113,38.35 ; 112.75,38.1 113,38.35
N00100025: C379.2 IC311.5 PC304.4 Q312.2 R357.1 | length 27.3
  BOTTOM w0.25: PC304.4@104.73,37.6 104.73,38.5 104.48,38.75 102.85,38.75 102.6,39 Q312.2@102.6,40.15 102.6,41 102.85,41.25 107.5,41.25 107.75,41 C379.2@107.75,40.4 R357.1@109.75,40.4 109.75,35.5 109.25,35 109.25,34 113.225,30.025 IC311.5@115.15,30.025
N00100026: C313.2 IC301.8 R301.1 R364.2 | length 13.6
  TOP w0.25: R301.1@56.8,59.75 56.8,58.575 57.275,58.1 C313.2@57.275,56.75 IC301.8@60.4,56.75 61.25,56.75 61.375,56.875 61.375,61.75 61.625,62 R364.2@62.65,62
N00100028: C70.1 CN3.2 CN14.1 | length 24.8
  TOP w0.5: CN14.1@281.98,212.6 281.98,206.77 282.5,206.25 283,206.25 ; CN3.2@283.5,203.5 283.5,205.75 ; C70.1@294.5,203.35 294.5,205.75 294,206.25 284,206.25 ; 283,206.25 283.5,205.75 ; 283,206.25 284,206.25 ; 283.5,205.75 284,206.25
N00100030: D302.2 D303.2 D304.2 IC302.3 R311.1 R314.1 R317.1 | length 43.8
  TOP w0.5: R311.1@176.75,67.55 176.75,68.35 177.4,69 D302.2@177.4,70.5 177.4,72 177.65,72.25 184.9,72.25 ; R314.1@184.5,67.55 184.5,68.35 185.15,69 D303.2@185.15,70.5 185.15,72 ; R317.1@192.25,67.55 192.25,68.35 192.9,69 D304.2@192.9,70.5 ; IC302.3@197.365,60.1 197.365,67.635 194.5,70.5 D304.2@192.9,70.5 ; 184.9,72.25 185.15,72 ; 184.9,72.25 185.4,72.25 ; 185.15,72 185.4,72.25 ; 185.4,72.25 192.65,72.25 192.9,72 D304.2@192.9,70.5
N00100031: D306.2 D307.2 D308.2 IC302.8 R321.1 R324.1 R327.1 | length 41.2
  TOP w0.5: R321.1@176,45.95 v1(176,44.375) 176.65,43.725 D306.2@176.65,42.5 ; R324.1@183,45.95 v1(183,44.375) 183.65,43.725 D307.2@183.65,42.5 ; D308.2@190.65,42.5 190.65,43.725 v1(190,44.375) R327.1@190,45.95 191.575,45.95 192.875,47.25 192.875,49.625 195.5,52.25 v1(195.5,53.125) ; v1(199.905,53.125) IC302.8@199.905,54.4
  BOTTOM w0.5: v1(176,44.375) v1(183,44.375) v1(190,44.375) ; v1(195.5,53.125) v1(199.905,53.125)
N00100032: C341.1 C439.1 D305.2 IC302.2 | length 17.5
  TOP w0.5: C341.1@197.225,76.25 197.225,74.425 196.55,73.75 D305.2@196.55,72.5 196.55,70.5 198.625,68.425 198.944,68.106 C439.1@198.944,63.34 198.944,61.617 198.635,61.308 IC302.2@198.635,60.1
N00100034: IC302.6 IC313.4 | length 22.3
  TOP w0.25: IC313.4@192.275,35.1 193.75,35.1 194,35.35 194,49.125 197.365,52.49 IC302.6@197.365,54.4
N00100035: IC302.5 IC313.6 | length 20.3
  TOP w0.25: IC313.6@192.275,36.4 193.25,36.4 193.5,36.65 193.5,49.375 196.25,52.125 196.25,53.5 196.095,53.655 IC302.5@196.095,54.4
N00100039: D6.2 D7.2 D8.2 IC2.8 R21.1 R24.1 R27.1 | length 41.2
  TOP w0.5: R21.1@176,225.95 v1(176,224.375) 176.65,223.725 D6.2@176.65,222.5 ; R24.1@183,225.95 v1(183,224.375) 183.65,223.725 D7.2@183.65,222.5 ; D8.2@190.65,222.5 190.65,223.725 v1(190,224.375) R27.1@190,225.95 191.575,225.95 192.875,227.25 192.875,229.75 195.5,232.375 v1(195.5,233.125) ; v1(199.905,233.125) IC2.8@199.905,234.4
  BOTTOM w0.5: v1(176,224.375) v1(183,224.375) v1(190,224.375) ; v1(195.5,233.125) v1(199.905,233.125)
N00100041: C316.1 C317.1 IC301.1 L301.1 R308.2 | length 72.6
  TOP w0.25: v1(58.625,61.625) 58.625,61.25 59.625,60.25 IC301.1@60.4,60.25
  TOP w1: 73.15,62.7 L301.1@80.5,62.7 ; 80.5,60.15 L301.1@80.5,62.7 ; v1@80.5,65.25 v1(80.5,65.125) L301.1@80.5,62.7 ; 81,37.5 85.15,37.5 ; 81,52.5 85.15,52.5 ; 85.15,33.043 85.15,37.5 ; 85.15,41.957 85.15,37.5 ; 85.15,48.043 85.15,52.5 ; 85.15,56.957 85.15,52.5 ; 87.85,62.7 L301.1@80.5,62.7 ; 89,37.5 C317.1@86.3,37.5 85.15,37.5 ; 89,52.5 C316.1@86.3,52.5 85.15,52.5
  BOTTOM w0.25: v1(58.625,61.625) 61.5,64.5 61.5,74.25 61.75,74.5 R308.2@64,74.5
  other v1: 82.5,30.375 88.5,30.375 81.5,31.25 83.5,31.25 85.5,31.25 87.5,31.25 82.5,32.25 84.5,32.25 86.5,32.25 88.5,32.25 81.5,33.25 83.5,33.25 85.5,33.25 87.5,33.25 82.5,34.25 82.5,40.25 81.5,41.25 82.5,42.25 84.5,42.25 86.5,42.25 88.5,42.25 81.5,43.25 83.5,43.25 85.5,43.25 87.5,43.25 82.5,44.25 84.5,44.25 86.5,44.25 88.5,44.25 81.5,45.25 83.5,45.25 85.5,45.25 87.5,45.25 82.5,46.25 84.5,46.25 86.5,46.25 88.5,46.25 81.5,47.25 83.5,47.25 85.5,47.25 87.5,47.25 82.5,48.25 84.5,48.25 86.5,48.25 88.5,48.25 81.5,49.25 81.5,55.25 62.5,65.125 64.5,65.125 70.5,65.125 72.5,65.125 74.5,65.125 76.5,65.125 78.5,65.125 82.5,65.125 84.5,65.125 86.5,65.125 88.5,65.125 63.5,66 65.5,66 71.5,66 73.5,66.125 75.5,66.125 77.5,66.125 79.5,66.125 81.5,66.125 83.5,66.125 85.5,66.125 87.5,66.125 62.5,67 64.5,67 66.5,67 68.5,67 70.5,67 72.5,67 74.5,67.125 76.5,67.125 78.5,67.125 80.5,67.125 82.5,67.125 84.5,67.125 86.5,67.125 88.5,67.125 63.5,68 65.5,68 67.5,68 69.5,68 71.5,68 73.5,68.125 75.5,68.125 77.5,68.125 79.5,68.125 81.5,68.125 83.5,68.125 85.5,68.125 87.5,68.125 62.5,69 64.5,69 66.5,69 68.5,69 70.5,69 63.5,70 65.5,70 67.5,70 69.5,70 71.5,70 62.5,71 64.5,71 66.5,71 68.5,71 70.5,71 67.5,72 69.5,72 71.5,72 68.5,73 70.5,73 67.5,74 69.5,74 71.5,74 68.5,75 70.5,75 67.5,76 69.5,76 71.5,76 68.5,77 70.5,77 63.5,78 65.5,78 67.5,78 69.5,78 71.5,78 62.5,79 64.5,79 66.5,79 68.5,79 70.5,79
N00100042: IC301.2 IC301.5 Q301.S Q302.S R307.2 R308.1 | length 44.3
  TOP w0.25: 54.1,68.975 R307.2@54.1,69.75 ; 54.1,70.525 R307.2@54.1,69.75 ; 54.925,69.75 R307.2@54.1,69.75 ; v1(58.625,58.875) 59.25,58.25 IC301.5@60.4,58.25 ; v1(58.625,60.25) 59.125,59.75 IC301.2@60.4,59.75
  BOTTOM w0.25: R308.1@58,74 60.25,74 60.5,73.75 60.5,65.5 57.25,62.25 57.25,60.25 v1(58.625,58.875) ; R308.1@58,74.5 60.5,74.5 61,74 61,65 57.875,61.875 57.875,61 v1(58.625,60.25)
  other v1: 55.5,70 57.5,70 59.5,70 54.5,71 56.5,71 58.5,71 53.5,72 54.5,73 54.5,75 53.5,76 52.5,77 54.5,77 53.5,78 55.5,78 57.5,78 59.5,78 52.5,79 54.5,79 56.5,79 58.5,79
N00100043: D325.2 IC301.6 Q301.G Q302.G R307.1 R437.1 | length 35.1
  TOP w0.25: v1(52.4,74.595) R307.1@52.4,69.75 52.4,68.12 52.388,68.108 52.375,68.095 v1(52.4,68.095) 57.625,68.095 57.875,67.845 57.875,58.25 58.625,57.5 59.375,57.5 59.625,57.75 IC301.6@60.4,57.75
  TOP w0.5: v1(52.4,68.095) 53.599,66.896 55.306,66.896 55.975,66.227 R437.1@55.975,64.927 55.975,64.009 55.775,63.809 D325.2@55.775,62.705
  BOTTOM w0.25: Q302.G@51.15,68.095 v1(52.4,68.095) ; Q301.G@51.15,74.595 v1(52.4,74.595)
N00100044: D307.1 R323.1 | length 3.7
  TOP w0.5: D307.1@179.35,42.5 179.35,43.725 180,44.375 R323.1@180,45.95
N00100045: D305.1 R309.2 | length 3
  TOP w0.5: D305.1@200.95,72.5 200.95,71 201,70.95 R309.2@201,69.55
N00100046: D302.1 R310.1 | length 3.2
  TOP w0.5: D302.1@173.1,70.5 173.1,69 173.75,68.35 R310.1@173.75,67.55
N00100048: D303.1 R313.1 | length 3.2
  TOP w0.5: D303.1@180.85,70.5 180.85,69 181.5,68.35 R313.1@181.5,67.55
N00100049: D304.1 R316.1 | length 3.2
  TOP w0.5: D304.1@188.6,70.5 188.6,69 189.25,68.35 R316.1@189.25,67.55
N00100050: D306.1 R320.1 | length 3.7
  TOP w0.5: D306.1@172.35,42.5 172.35,43.725 173,44.375 R320.1@173,45.95
N00100051: D308.1 R326.1 | length 3.7
  TOP w0.5: D308.1@186.35,42.5 186.35,43.725 187,44.375 R326.1@187,45.95
N00100059: C443.1 CN321.1 D319.1 D320.1 Q313.1 Q314.1 Q315.1 Q316.1 Q320.3 R363.2 R392.2 | length 75.2
  TOP w0.5: v1(283.25,54.125) 292.75,54.125 293.25,54.625 Q314.1@293.25,56.3 v1(294.875,56.3) ; Q313.1@293.25,67.8 v1(294.875,67.8) ; v1(298.125,64.7) Q316.1@299.75,64.7 ; Q315.1@299.75,76.2 v1(298.125,76.2) 298.125,77 ; 298.125,77 CN321.1@298.125,78.375 ; 298.125,77 297.5,77.625 297.5,78.375 CN321.1@298.125,78.375 ; 298.125,77 298.75,77.625 298.75,78.375 CN321.1@298.125,78.375
  BOTTOM w0.5: R392.2@268.75,59.6 270.405,59.6 ; C443.1@270.405,61.775 270.405,59.6 ; v1(283.25,54.125) 283.25,59.55 282.75,60.05 279.7,60.05 279.25,59.6 R363.2@277.75,59.6 D319.1@275.75,59.6 D320.1@273.5,59.6 270.405,59.6 ; v1(294.875,56.3) 296,56.3 296.5,56.8 296.5,64.2 ; v1(294.875,67.8) 296,67.8 ; v1(298.125,64.7) 297,64.7 ; v1(298.125,76.2) 297,76.2 296.5,75.7 296.5,68.3 ; 296,67.8 296.5,67.3 ; 296,67.8 296.5,68.3 ; 296.5,64.2 297,64.7 ; 296.5,64.2 296.5,65.2 ; 296.5,65.2 296.5,67.3 ; 296.5,65.2 297,64.7 ; 296.5,67.3 296.5,68.3
N00100060: CN322.1 D318.1 D321.1 Q313.2 Q314.2 Q315.2 Q316.2 Q320.2 R363.1 | length 31
  TOP w0.5: v1(277.6,53.25) 294,53.25
  TOP w1: 294.65,54 CN322.1@298,54 298,55.75
  BOTTOM w0.5: v1(277.6,53.25) D321.1@277.6,55.75 ; R363.1@277.75,57.9 277.75,56.875 277.6,56.725 D321.1@277.6,55.75 ; Q320.2@280.35,57.95 Q320.2@280.35,57.9 280.35,57 280.15,56.8 D318.1@280.15,55.75 D321.1@277.6,55.75
N00100065: PC303.6 Q311.1 | length 3.7
  BOTTOM w0.25: Q311.1@100.9,40.2 Q311.1@100.9,40.15 100.9,39 101.15,38.75 102.02,38.75 102.27,38.5 PC303.6@102.27,37.6
N00100066: Q311.3 R349.2 | length 16.7
  BOTTOM w0.25: Q311.3@100.25,42.3 Q311.3@100.25,42.35 100.25,43 100.5,43.25 112.25,43.25 112.5,43 112.5,40.875 112.975,40.4 R349.2@113.75,40.4
N00100072: Q312.3 R356.2 | length 2.6
  BOTTOM w0.25: Q312.3@103.25,42.3 104.5,42.3 104.7,42.1 R356.2@105.75,42.1
N00100073: PC304.6 Q312.1 | length 4.9
  BOTTOM w0.25: Q312.1@103.9,40.2 Q312.1@103.9,40.15 103.9,39.5 104.15,39.25 104.75,39.25 106.4,37.6 PC304.6@107.27,37.6
N00100074: C314.1 IC301.15 | length 2.4
  TOP w0.25: IC301.15@65.1,59.75 C314.1@67.525,59.75
N00100075: IC301.9 IC301.10 PC301.4 Q317.2 R365.2 | length 61.2
  TOP w0.25: IC301.9@65.1,56.75 v1(66.25,56.75) ; IC301.10@65.1,57.25 66.125,57.25 66.25,57.125 v1(66.25,56.75) ; Q317.2@68.55,65.15 67.65,65.15 67.4,64.9 R365.2@67.4,62 67.4,61.25 67.65,61 68.25,61 68.5,60.75 68.5,57 68.25,56.75 v1(66.25,56.75)
  BOTTOM w0.25: v1(66.25,56.75) 66.625,57.125 88.875,57.125 89.875,56.125 89.875,41.875 90.375,41.375 92.875,41.375 93.25,41 93.25,40 94.73,38.52 PC301.4@94.73,37.6
N00100080: IC301.13 R370.1 | length 3.5
  TOP w0.25: IC301.13@65.1,58.75 66.25,58.75 66.5,58.5 66.5,57.75 66.75,57.5 R370.1@67.65,57.5
N00100084: C315.2 IC301.11 R302.1 R303.2 | length 9.3
  TOP w0.25: IC301.11@65.1,57.75 64.375,57.75 64.125,57.5 64.125,56.5 64.375,56.25 65.35,56.25 65.6,56 R302.1@65.6,54.5 C315.2@67.65,54.5 R303.2@67.65,52.5
N00100088: D320.2 R382.2 | length 4.5
  BOTTOM w0.5: R382.2@271,55.8 271,57.65 271.25,57.9 D320.2@273.5,57.9
N00100089: IC312.12 R381.1 R382.1 | length 5.1
  BOTTOM w0.25: R382.1@271,53.7 271,52.675 271.425,52.25 IC312.12@271.425,51.05
  BOTTOM w0.5: R381.1@268.75,53.65 269.625,53.65 269.675,53.7 R382.1@271,53.7
N00100093: C382.2 IC312.1 | length 8.1
  BOTTOM w0.25: IC312.1@274.025,44.95 274.025,48.025 275.5,49.5 275.5,51.35 275.75,51.6 C382.2@276.5,51.6
N00100094: C382.1 IC312.3 | length 10.1
  BOTTOM w0.25: IC312.3@272.725,44.95 272.725,44.125 273.1,43.75 274.5,43.75 274.75,44 274.75,48 275.625,48.875 276.25,48.875 276.5,49.125 C382.1@276.5,49.9
N00100095: C381.2 IC312.4 R360.2 | length 17.5
  BOTTOM w0.25: IC312.4@272.075,44.95 272.075,44.05 272.875,43.25 274.75,43.25 275.25,43.75 275.25,47.05 275.5,47.3 R360.2@276.5,47.3 277.625,47.3 277.875,47.55 277.875,51.05 278.125,51.3 C381.2@281,51.3
N00100097: C383.1 IC312.13 | length 5.8
  BOTTOM w0.25: C383.1@267.75,48.85 270.85,48.85 272.075,50.075 IC312.13@272.075,51.05
N00100098: C384.1 IC312.14 | length 3.2
  BOTTOM w0.25: IC312.14@272.725,51.05 272.725,53.15 272.975,53.4 C384.1@273.75,53.4
N00100099: C384.2 IC312.16 | length 5.2
  BOTTOM w0.25: C384.2@273.75,55.1 274.525,55.1 274.75,54.875 274.75,52.75 274.025,52.025 IC312.16@274.025,51.05
N00100100: IC312.6 PC306.3 R388.2 | length 11.9
  BOTTOM w0.25: R388.2@267.5,40.4 268.125,40.4 ; PC306.3@269.865,37.35 269.865,38.75 269.615,39 268.875,39 268.375,39.5 268.375,40.15 ; IC312.6@270.775,44.95 270.775,43.25 270.525,43 268.875,43 268.375,42.5 268.375,40.65 ; 268.125,40.4 268.375,40.65 ; 268.125,40.4 268.375,40.15 ; 268.375,40.15 268.375,40.65
N00100101: IC312.5 PC305.3 R389.2 | length 12.2
  BOTTOM w0.25: IC312.5@271.425,44.95 271.425,43.95 272.625,42.75 272.625,40.65 272.875,40.4 R389.2@273.75,40.4 273.75,39.375 274,39.125 275,39.125 276.125,38 277.5,38 277.865,37.635 PC305.3@277.865,37.35
N00100104: IC312.10 R390.1 | length 10.2
  TOP w0.25: v1(270.125,49.875) 270.75,49.25 v1(270.75,42.1)
  BOTTOM w0.25: v1(270.125,49.875) IC312.10@270.125,51.05 ; v1(270.75,42.1) R390.1@271.75,42.1
N00100114: R348.2 R349.1 | length 2
  BOTTOM w0.25: R349.1@113.75,42.1 R348.2@115.75,42.1
N00100115: R351.2 R352.1 | length 2
  BOTTOM w0.25: R352.1@120.25,38.35 R351.2@120.25,40.4
N00100116: R303.1 R304.2 | length 2
  TOP w0.25: R304.2@69.35,50.5 R303.1@69.35,52.5
N00100119: IC313.3 IC314.6 | length 2.3
  TOP w0.25: IC314.6@187.9,35.115 188.985,35.115 189,35.1 IC313.3@190.225,35.1
N00100120: Q318.6 R367.2 | length 19
  TOP w0.25: v1(97.875,26.5) 99.625,28.25 110.875,28.25 v1(112.75,26.375)
  BOTTOM w0.25: R367.2@96.85,26.5 v1(97.875,26.5) ; Q318.6@111.775,27.1 112.5,27.1 112.75,26.85 v1(112.75,26.375)
N00100121: IC313.1 IC314.7 | length 2.3
  TOP w0.25: IC314.7@187.9,36.385 189,36.385 189.015,36.4 IC313.1@190.225,36.4
N00100124: Q317.3 R364.1 | length 4.5
  TOP w0.25: R364.1@64.35,62 66.25,62 66.45,62.2 Q317.3@66.45,64.5
N00100125: PC301.6 Q317.1 | length 52.4
  TOP w0.25: Q317.1@68.55,63.85 Q317.1@68.6,63.85 70.525,63.85 71,63.375 v1(71,57.75)
  BOTTOM w0.25: v1(71,57.75) 89,57.75 90.375,56.375 90.375,42.125 90.625,41.875 93.125,41.875 93.75,41.25 93.75,40.25 95.125,38.875 97.02,38.875 97.27,38.625 PC301.6@97.27,37.6
N00100127: PC301.3 R366.1 R367.1 | length 4.6
  BOTTOM w0.25: PC301.3@94.715,30.9 94.715,29.91 95.15,29.475 R366.1@95.15,28.5 R367.1@95.15,26.5
N00100130: Q318.3 R369.1 R372.1 | length 10.3
  TOP w0.25: v1(101.85,27.5) v1(106.85,27.5) v1@106.875,27.5
  BOTTOM w0.25: R369.1@101.85,26.5 v1(101.85,27.5) ; R372.1@106.85,26.5 v1(106.85,27.5) 107.75,27.5 108.65,28.4 Q318.3@109.725,28.4
N00100132: PC302.2 R370.2 R371.1 | length 42
  TOP w0.25: v1(69.35,56.5) R370.2@69.35,57.5
  BOTTOM w0.25: v1(69.35,56.5) 88.75,56.5 89.375,55.875 89.375,41.625 90.125,40.875 92.125,40.875 92.35,40.65 R371.1@92.35,40 92.35,39.2 92.15,39 PC302.2@92.15,37.6
N00100136: PC303.3 R368.1 R369.2 | length 4.6
  BOTTOM w0.25: PC303.3@99.715,30.9 99.715,29.91 100.15,29.475 R368.1@100.15,28.5 R369.2@100.15,26.5
N00100138: D317.2 R381.2 R392.1 | length 4.8
  BOTTOM w0.5: D317.2@266.5,55.35 R381.2@268.75,55.35 R392.1@268.75,57.9
N00100140: D318.2 Q320.1 R393.2 | length 4.5
  BOTTOM w0.5: Q320.1@281.65,57.95 Q320.1@281.65,57.9 281.65,57 281.85,56.8 D318.2@281.85,55.75 R393.2@281.85,53.5
N00100146: PC307.2 R390.2 R391.1 | length 8.2
  BOTTOM w0.25: R391.1@269.75,40.4 R390.2@271.75,40.4 271.75,38.75 272,38.5 274.9,38.5 275.15,38.25 PC307.2@275.15,37.35
N00100153: PC304.3 R372.2 R373.1 | length 4.6
  BOTTOM w0.25: PC304.3@104.715,30.9 104.715,29.875 105.15,29.44 R373.1@105.15,28.5 R372.2@105.15,26.5
N00100155: PC305.2 R384.2 R386.1 | length 7.6
  BOTTOM w0.25: PC305.2@277.85,30.65 277.85,29.125 278.1,28.875 279.25,28.875 279.5,28.625 R384.2@279.5,27.85 280.275,27.85 280.5,27.625 280.5,26.375 280.725,26.15 R386.1@281.5,26.15
N00100156: Q319.3 R384.1 | length 2.3
  BOTTOM w0.25: Q319.3@277.275,26.35 278.25,26.35 278.45,26.15 R384.1@279.5,26.15
N00100157: PC306.2 R385.2 R387.1 | length 7.5
  BOTTOM w0.25: PC306.2@269.85,30.65 269.85,26.375 270.075,26.15 R387.1@271,26.15 R385.2@273,26.15
N00100158: Q319.6 R385.1 | length 2.3
  BOTTOM w0.25: R385.1@273,27.85 273.9,27.85 274.1,27.65 Q319.6@275.225,27.65
N00100162: D319.2 D321.2 | length 2.2
  BOTTOM w0.5: D319.2@275.75,57.9 275.75,56.875 275.9,56.725 D321.2@275.9,55.75
N00100164: CN305.2 R5411.1 | length 14.5
  BOTTOM w0.25: CN305.2@181.75,83 181.75,79.875 182,79.625 190.229,79.625 191.15,78.704 R5411.1@191.15,77.25
N00100165: CN305.1 R5411.2 | length 12.9
  BOTTOM w0.25: CN305.1@184.25,83 184.25,80.625 184.5,80.375 190.604,80.375 192.85,78.129 R5411.2@192.85,77.25
N00100178: C397.1 CN304.2 CN313.1 | length 14.1
  TOP w0.5: C397.1@88.4,25 90.5,25 91.48,25.98 94.77,25.98 ; CN313.1@95.27,29.65 95.27,26.48 ; CN304.2@97,24.25 95.27,25.98 ; 94.77,25.98 95.27,25.98 ; 94.77,25.98 95.27,26.48 ; 95.27,25.98 95.27,26.48
N00100180: C371.1 CN303.7 CN315.1 | length 23
  TOP w0.5: C371.1@255.5,25.5 v1(258.25,25.5) ; CN303.7@271,23.5 271,26.75 272.27,28.02 CN315.1@272.27,29.65
  BOTTOM w0.5: v1(258.25,25.5) 269,25.5 CN303.7@271,23.5
N00100183: C399.1 CN301.5 CN312.1 | length 15.8
  TOP w0.5: CN301.5@172.25,24.5 172.25,25.875 174.355,27.98 178.75,27.98 ; C399.1@179,31.225 179,28.23 ; CN312.1@182.15,27.98 179.25,27.98 ; 178.75,27.98 179.25,27.98 ; 178.75,27.98 179,28.23 ; 179,28.23 179.25,27.98
N00100184: C398.1 CN301.4 CN311.1 | length 15.9
  TOP w0.5: CN311.1@162.65,30.23 168.62,30.23 169.25,29.6 ; CN301.4@169.75,24.5 169.75,29.1 ; C398.1@172.25,29.6 170.25,29.6 ; 169.25,29.6 169.75,29.1 ; 169.25,29.6 170.25,29.6 ; 169.75,29.1 170.25,29.6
